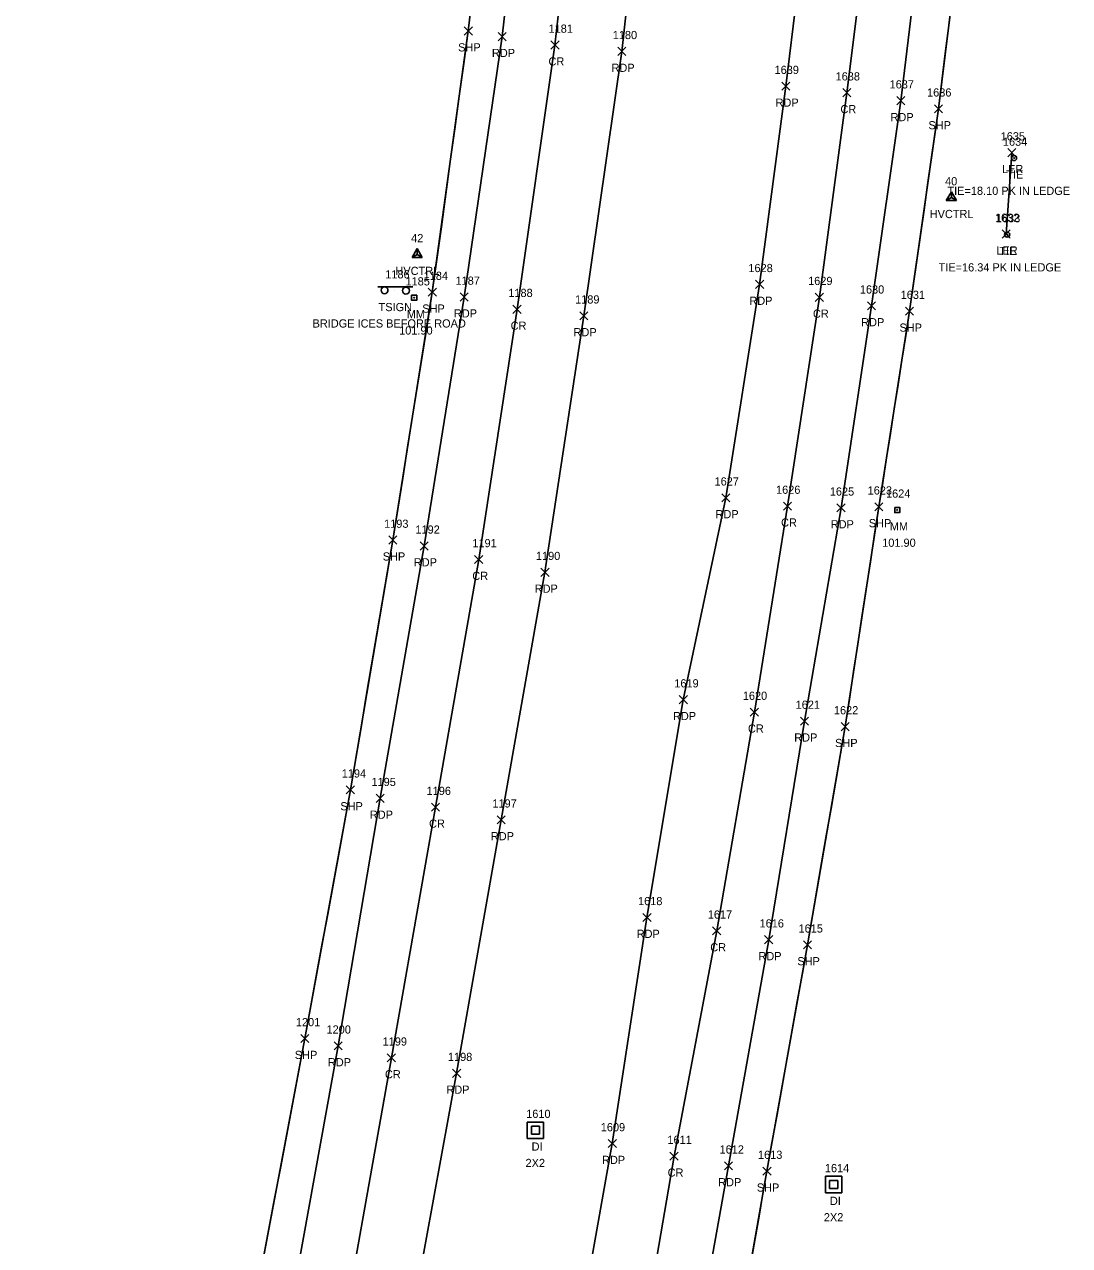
# Model space of a CAD drawing. Extents: x 1472022 to 1479249, y 777216 to 786527.
# Drawn here: x 1473774.1 to 1474029.4, y 780876.1 to 781174.4 of the extents above; entities that cross this region are included whole.
import ezdxf

# ---------------------------------------------------------------- set-up
doc = ezdxf.new("R2010")
doc.units = 0
for name, color, linetype in [('C_A', 7, 'Continuous'), ('C_C', 7, 'Continuous'), ('C_I', 7, 'Continuous'), ('CBP', 7, 'Continuous'), ('CPSM', 7, 'Continuous'), ('D_A', 7, 'Continuous'), ('D_C', 7, 'Continuous'), ('D_I', 7, 'Continuous'), ('DS', 7, 'Continuous'), ('L_A', 7, 'Continuous'), ('L_I', 7, 'Continuous'), ('L_TIC', 7, 'Continuous'), ('LARO', 7, 'Continuous'), ('LSOGP', 7, 'Continuous'), ('P_A', 7, 'Continuous'), ('P_I', 7, 'Continuous'), ('P_TIC', 7, 'Continuous'), ('PET', 7, 'Continuous'), ('PRC', 7, 'Continuous'), ('PSP', 7, 'Continuous'), ('S_A', 7, 'Continuous'), ('S_C', 7, 'Continuous'), ('S_I', 7, 'Continuous'), ('SRM', 7, 'Continuous'), ('SSGN', 7, 'Continuous')]:
    doc.layers.add(name, color=color, linetype=linetype)

msp = doc.modelspace()

# ---------------------------------------------------------------- linework, layer by layer
at = {"layer": 'CBP'}
for centre, radius in [((1474015.88, 781141.74), 0.625), ((1474015.88, 781141.74), 0.0833), ((1474014.18, 781123.04), 0.625), ((1474014.18, 781123.04), 0.0833)]:
    msp.add_circle(centre, radius, dxfattribs=at)
at = {"layer": 'CPSM'}
for p, q in [((1473999.32, 781131.35), (1474000.57, 781133.52)), ((1474001.82, 781131.35), (1474000.57, 781133.52)), ((1474000.57, 781132.07), (1474000.57, 781133.52)), ((1473999.32, 781131.35), (1474000.57, 781132.07)), ((1473999.32, 781131.35), (1474001.82, 781131.35)), ((1474000.57, 781132.07), (1474000.57, 781132.07)), ((1474000.57, 781132.07), (1474001.82, 781131.35)), ((1473868.79, 781117.46), (1473870.04, 781119.62)), ((1473868.79, 781117.46), (1473870.04, 781118.18)), ((1473871.29, 781117.46), (1473870.04, 781119.62)), ((1473870.04, 781118.18), (1473870.04, 781119.62)), ((1473870.04, 781118.18), (1473870.04, 781118.18)), ((1473870.04, 781118.18), (1473871.29, 781117.46)), ((1473868.79, 781117.46), (1473871.29, 781117.46))]:
    msp.add_line(p, q, dxfattribs=at)
at = {"layer": 'DS'}
for p, q in [((1473896.94, 780906.27), (1473900.94, 780906.27)), ((1473896.94, 780902.27), (1473896.94, 780906.27)), ((1473900.94, 780906.27), (1473900.94, 780902.27)), ((1473897.94, 780903.27), (1473897.94, 780905.27)), ((1473897.94, 780905.27), (1473899.94, 780905.27)), ((1473899.94, 780903.27), (1473897.94, 780903.27)), ((1473898.94, 780904.27), (1473898.94, 780904.27)), ((1473898.94, 780904.27), (1473898.94, 780904.27)), ((1473899.94, 780905.27), (1473899.94, 780903.27)), ((1473900.94, 780902.27), (1473896.94, 780902.27)), ((1473969.82, 780893.01), (1473973.82, 780893.01)), ((1473969.82, 780889.01), (1473969.82, 780893.01)), ((1473970.82, 780890.01), (1473970.82, 780892.01)), ((1473970.82, 780892.01), (1473972.82, 780892.01)), ((1473972.82, 780892.01), (1473972.82, 780890.01)), ((1473973.82, 780893.01), (1473973.82, 780889.01)), ((1473973.82, 780889.01), (1473969.82, 780889.01)), ((1473972.82, 780890.01), (1473970.82, 780890.01)), ((1473971.82, 780891.01), (1473971.82, 780891.01)), ((1473971.82, 780891.01), (1473971.82, 780891.01))]:
    msp.add_line(p, q, dxfattribs=at)
at = {"layer": 'L_TIC'}
for points in [[(1474014.34, 781142.05), (1474016.34, 781144.05)], [(1474016.34, 781142.05), (1474014.34, 781144.05)], [(1474012.96, 781122.17), (1474014.96, 781124.17)], [(1474014.96, 781122.17), (1474012.96, 781124.17)]]:
    msp.add_lwpolyline(points, dxfattribs=at)
at = {"layer": 'LARO'}
msp.add_lwpolyline([(1474013.96, 781123.17), (1474015.34, 781143.05)], dxfattribs=at)
at = {"layer": 'LSOGP'}
for points in [[(1473951.63, 780872.29), (1473952.59, 780877.78), (1473953.56, 780883.28), (1473954.52, 780888.77), (1473955.49, 780894.27), (1473956.73, 780901.18), (1473957.96, 780908.09), (1473959.2, 780915), (1473960.44, 780921.91), (1473961.68, 780928.82), (1473962.91, 780935.73), (1473964.15, 780942.64), (1473965.39, 780949.55), (1473966.54, 780956.22), (1473967.69, 780962.88), (1473968.84, 780969.54), (1473970, 780976.21), (1473971.15, 780982.87), (1473972.3, 780989.53), (1473973.45, 780996.19), (1473974.6, 781002.86), (1473975.63, 781009.57), (1473976.66, 781016.28), (1473977.69, 781022.99), (1473978.72, 781029.7), (1473979.75, 781036.42), (1473980.78, 781043.13), (1473981.81, 781049.84), (1473982.84, 781056.55), (1473983.78, 781062.52), (1473984.72, 781068.5), (1473985.66, 781074.47), (1473986.59, 781080.44), (1473987.53, 781086.41), (1473988.47, 781092.38), (1473989.41, 781098.36), (1473990.34, 781104.33), (1473991.23, 781110.51), (1473992.11, 781116.69), (1473993, 781122.87), (1473993.88, 781129.05), (1473994.76, 781135.23), (1473995.65, 781141.41), (1473996.53, 781147.58), (1473997.41, 781153.76), (1473998.24, 781160.53), (1473999.08, 781167.31), (1473999.91, 781174.08), (1474000.74, 781180.85)], [(1473883.42, 781180.21), (1473882.53, 781172.78), (1473881.43, 781164.8), (1473880.33, 781156.83), (1473879.24, 781148.85), (1473878.14, 781140.88), (1473877.04, 781132.9), (1473875.95, 781124.92), (1473874.85, 781116.95), (1473873.75, 781108.97), (1473872.54, 781101.4), (1473871.34, 781093.83), (1473870.13, 781086.26), (1473868.92, 781078.7), (1473867.71, 781071.13), (1473866.51, 781063.56), (1473865.3, 781055.99), (1473864.09, 781048.42), (1473862.8, 781040.79), (1473861.5, 781033.17), (1473860.21, 781025.54), (1473858.92, 781017.91), (1473857.62, 781010.29), (1473856.33, 781002.66), (1473855.04, 780995.03), (1473853.74, 780987.41), (1473852.35, 780979.81), (1473850.96, 780972.22), (1473849.57, 780964.63), (1473848.18, 780957.04), (1473846.79, 780949.45), (1473845.39, 780941.86), (1473844, 780934.26), (1473842.61, 780926.67), (1473841.13, 780918.86), (1473839.66, 780911.04), (1473838.18, 780903.23), (1473836.7, 780895.41), (1473835.22, 780887.6), (1473833.75, 780879.79), (1473832.27, 780871.97)]]:
    msp.add_lwpolyline(points, dxfattribs=at)
at = {"layer": 'P_TIC'}
for points in [[(1473881.53, 781171.78), (1473883.53, 781173.78)], [(1473883.53, 781171.78), (1473881.53, 781173.78)], [(1473889.82, 781170.41), (1473891.82, 781172.41)], [(1473891.82, 781170.41), (1473889.82, 781172.41)], [(1473902.7, 781168.35), (1473904.7, 781170.35)], [(1473904.7, 781168.35), (1473902.7, 781170.35)], [(1473919.04, 781166.79), (1473921.04, 781168.79)], [(1473921.04, 781166.79), (1473919.04, 781168.79)], [(1473959.11, 781158.28), (1473961.11, 781160.28)], [(1473961.11, 781158.28), (1473959.11, 781160.28)], [(1473974.01, 781156.69), (1473976.01, 781158.69)], [(1473976.01, 781156.69), (1473974.01, 781158.69)], [(1473987.2, 781154.74), (1473989.2, 781156.74)], [(1473989.2, 781154.74), (1473987.2, 781156.74)], [(1473996.41, 781152.76), (1473998.41, 781154.76)], [(1473998.41, 781152.76), (1473996.41, 781154.76)], [(1473952.71, 781109.88), (1473954.71, 781111.88)], [(1473954.71, 781109.88), (1473952.71, 781111.88)], [(1473872.75, 781107.97), (1473874.75, 781109.97)], [(1473874.75, 781107.97), (1473872.75, 781109.97)], [(1473880.54, 781106.79), (1473882.54, 781108.79)], [(1473882.54, 781106.79), (1473880.54, 781108.79)], [(1473967.3, 781106.73), (1473969.3, 781108.73)], [(1473969.3, 781106.73), (1473967.3, 781108.73)], [(1473980.03, 781104.64), (1473982.03, 781106.64)], [(1473982.03, 781104.64), (1473980.03, 781106.64)], [(1473893.45, 781103.8), (1473895.45, 781105.8)], [(1473895.45, 781103.8), (1473893.45, 781105.8)], [(1473909.76, 781102.2), (1473911.76, 781104.2)], [(1473911.76, 781102.2), (1473909.76, 781104.2)], [(1473989.34, 781103.33), (1473991.34, 781105.33)], [(1473991.34, 781103.33), (1473989.34, 781105.33)], [(1473944.44, 781057.75), (1473946.44, 781059.75)], [(1473946.44, 781057.75), (1473944.44, 781059.75)], [(1473959.52, 781055.72), (1473961.52, 781057.72)], [(1473961.52, 781055.72), (1473959.52, 781057.72)], [(1473972.6, 781055.28), (1473974.6, 781057.28)], [(1473974.6, 781055.28), (1473972.6, 781057.28)], [(1473981.84, 781055.55), (1473983.84, 781057.55)], [(1473983.84, 781055.55), (1473981.84, 781057.55)], [(1473863.09, 781047.42), (1473865.09, 781049.42)], [(1473865.09, 781047.42), (1473863.09, 781049.42)], [(1473870.75, 781045.99), (1473872.75, 781047.99)], [(1473872.75, 781045.99), (1473870.75, 781047.99)], [(1473884.09, 781042.68), (1473886.09, 781044.68)], [(1473886.09, 781042.68), (1473884.09, 781044.68)], [(1473900.27, 781039.55), (1473902.27, 781041.55)], [(1473902.27, 781039.55), (1473900.27, 781041.55)], [(1473934.05, 781008.43), (1473936.05, 781010.43)], [(1473936.05, 781008.43), (1473934.05, 781010.43)], [(1473951.43, 781005.39), (1473953.43, 781007.39)], [(1473953.43, 781005.39), (1473951.43, 781007.39)], [(1473963.68, 781003.2), (1473965.68, 781005.2)], [(1473965.68, 781003.2), (1473963.68, 781005.2)], [(1473973.6, 781001.86), (1473975.6, 781003.86)], [(1473975.6, 781001.86), (1473973.6, 781003.86)], [(1473852.74, 780986.41), (1473854.74, 780988.41)], [(1473854.74, 780986.41), (1473852.74, 780988.41)], [(1473860.01, 780984.34), (1473862.01, 780986.34)], [(1473862.01, 780984.34), (1473860.01, 780986.34)], [(1473873.53, 780982.16), (1473875.53, 780984.16)], [(1473875.53, 780982.16), (1473873.53, 780984.16)], [(1473889.55, 780979.09), (1473891.55, 780981.09)], [(1473891.55, 780979.09), (1473889.55, 780981.09)], [(1473925.18, 780955.24), (1473927.18, 780957.24)], [(1473927.18, 780955.24), (1473925.18, 780957.24)], [(1473942.22, 780951.96), (1473944.22, 780953.96)], [(1473944.22, 780951.96), (1473942.22, 780953.96)], [(1473954.93, 780949.79), (1473956.93, 780951.79)], [(1473956.93, 780949.79), (1473954.93, 780951.79)], [(1473964.39, 780948.55), (1473966.39, 780950.55)], [(1473966.39, 780948.55), (1473964.39, 780950.55)], [(1473841.61, 780925.67), (1473843.61, 780927.67)], [(1473843.61, 780925.67), (1473841.61, 780927.67)], [(1473849.75, 780923.87), (1473851.75, 780925.87)], [(1473851.75, 780923.87), (1473849.75, 780925.87)], [(1473862.74, 780920.94), (1473864.74, 780922.94)], [(1473864.74, 780920.94), (1473862.74, 780922.94)], [(1473878.69, 780917.18), (1473880.69, 780919.18)], [(1473880.69, 780917.18), (1473878.69, 780919.18)], [(1473916.72, 780900.01), (1473918.72, 780902.01)], [(1473918.72, 780900.01), (1473916.72, 780902.01)], [(1473931.8, 780896.93), (1473933.8, 780898.93)], [(1473933.8, 780896.93), (1473931.8, 780898.93)], [(1473945.09, 780894.57), (1473947.09, 780896.57)], [(1473947.09, 780894.57), (1473945.09, 780896.57)], [(1473954.49, 780893.27), (1473956.49, 780895.27)], [(1473956.49, 780893.27), (1473954.49, 780895.27)]]:
    msp.add_lwpolyline(points, dxfattribs=at)
at = {"layer": 'PET'}
for points in [[(1473897.58, 781231.34), (1473890.82, 781171.41), (1473881.54, 781107.79), (1473871.75, 781046.99), (1473861.01, 780985.34), (1473850.75, 780924.87), (1473839.34, 780861.82), (1473828.24, 780801.17), (1473817.32, 780741.26), (1473806.09, 780678.1), (1473794.13, 780615.24), (1473782.52, 780552.37)], [(1473926.74, 781228.4), (1473920.04, 781167.79), (1473910.76, 781103.2), (1473901.27, 781040.55), (1473890.55, 780980.09), (1473879.69, 780918.18), (1473868.45, 780856.64), (1473857.58, 780795.65), (1473846.42, 780735.85), (1473834.5, 780671.46), (1473823.42, 780612.39), (1473811.33, 780545.89)], [(1473858.97, 780579.12), (1473867.36, 780624.13), (1473877.11, 780675.98), (1473886.11, 780727.43), (1473894.33, 780770.7), (1473900.97, 780808.51), (1473909.58, 780855.22), (1473917.72, 780901.01), (1473926.18, 780956.24), (1473935.05, 781009.43), (1473945.44, 781058.75), (1473953.71, 781110.88), (1473960.11, 781159.28), (1473966.39, 781210.69)], [(1473887.71, 780574.3), (1473895.6, 780618.75), (1473905.45, 780670.32), (1473914.28, 780720.97), (1473922.71, 780765.55), (1473929.03, 780802.44), (1473938.07, 780850.55), (1473946.09, 780895.57), (1473955.93, 780950.79), (1473964.68, 781004.2), (1473973.6, 781056.28), (1473981.03, 781105.64), (1473988.2, 781155.74), (1473994.49, 781207.67)]]:
    msp.add_lwpolyline(points, dxfattribs=at)
at = {"layer": 'PRC'}
for points in [[(1473910.61, 781230.26), (1473903.7, 781169.35), (1473894.45, 781104.8), (1473885.09, 781043.68), (1473874.53, 780983.16), (1473863.74, 780921.94), (1473852.71, 780859.81), (1473841.54, 780798.62), (1473830.32, 780739.37), (1473818.72, 780674.7), (1473807.59, 780614.57), (1473795.53, 780548.63)], [(1473874.56, 780576.61), (1473882.64, 780621.02), (1473892.2, 780672.57), (1473901.35, 780723.23), (1473910.11, 780767.82), (1473915.89, 780804.48), (1473924.97, 780851.96), (1473932.8, 780897.93), (1473943.22, 780952.96), (1473952.43, 781006.39), (1473960.52, 781056.72), (1473968.3, 781107.73), (1473975.01, 781157.69), (1473981.49, 781209.1)]]:
    msp.add_lwpolyline(points, dxfattribs=at)
at = {"layer": 'PSP'}
for points in [[(1473889.69, 781232.26), (1473882.53, 781172.78), (1473873.75, 781108.97), (1473864.09, 781048.42), (1473853.74, 780987.41), (1473842.61, 780926.67), (1473830.79, 780864.16), (1473819.66, 780802.9), (1473808.62, 780742.26), (1473797.28, 780680.22), (1473785.49, 780617.45), (1473774.09, 780553.9)], [(1473897.21, 780573.03), (1473905.39, 780617.74), (1473914.98, 780669.02), (1473924.04, 780718.8), (1473932.36, 780764.14), (1473938.69, 780801.17), (1473947.77, 780850.3), (1473955.49, 780894.27), (1473965.39, 780949.55), (1473974.6, 781002.86), (1473982.84, 781056.55), (1473990.34, 781104.33), (1473997.41, 781153.76), (1474004.06, 781207.93)]]:
    msp.add_lwpolyline(points, dxfattribs=at)
at = {"layer": 'SRM'}
for points in [[(1473868.69, 781108.24), (1473869.94, 781108.24), (1473869.94, 781106.99), (1473868.69, 781106.99)], [(1473986.71, 781056.4), (1473987.96, 781056.4), (1473987.96, 781055.15), (1473986.71, 781055.15)]]:
    msp.add_lwpolyline(points, close=True, dxfattribs=at)
for centre in [(1473869.32, 781107.62), (1473987.33, 781055.78)]:
    msp.add_circle(centre, 0.0833, dxfattribs=at)
at = {"layer": 'SSGN'}
for p, q in [((1473860.42, 781110.26), (1473869.02, 781110.26)), ((1473864.44, 781109.36), (1473864.44, 781109.36))]:
    msp.add_line(p, q, dxfattribs=at)
for centre in [(1473862.08, 781109.43), (1473867.3, 781109.36)]:
    msp.add_circle(centre, 0.833, dxfattribs=at)

# ---------------------------------------------------------------- texts
at = {"layer": 'C_A'}
for s, p in [('TIE', (1474013.96, 781136.74)), ('HVCTRL', (1473995.27, 781127.07)), ('TIE', (1474012.26, 781118.04)), ('HVCTRL', (1473864.73, 781113.18))]:
    msp.add_text(s, height=2, dxfattribs=at).set_placement(p)
at = {"layer": 'C_C'}
for s, p in [('TIE=18.10 PK IN LEDGE', (1473999.6, 781132.74)), ('TIE=16.34 PK IN LEDGE', (1473997.44, 781114.04))]:
    msp.add_text(s, height=2, dxfattribs=at).set_placement(p)
at = {"layer": 'C_I'}
for s, p in [('1634', (1474013.14, 781144.74)), ('40', (1473999.02, 781135.07)), ('1633', (1474011.44, 781126.04)), ('42', (1473868.57, 781121.18))]:
    msp.add_text(s, height=2, dxfattribs=at).set_placement(p)
at = {"layer": 'D_A'}
for p in [(1473898, 780899.27), (1473970.88, 780886.01)]:
    msp.add_text('DI', height=2, dxfattribs=at).set_placement(p)
at = {"layer": 'D_C'}
for p in [(1473896.52, 780895.27), (1473969.4, 780882.01)]:
    msp.add_text('2X2', height=2, dxfattribs=at).set_placement(p)
at = {"layer": 'D_I'}
for s, p in [('1610', (1473896.68, 780907.27)), ('1614', (1473969.65, 780894.01))]:
    msp.add_text(s, height=2, dxfattribs=at).set_placement(p)
at = {"layer": 'L_A'}
for p in [(1474012.92, 781138.05), (1474011.55, 781118.17)]:
    msp.add_text('LER', height=2, dxfattribs=at).set_placement(p)
at = {"layer": 'L_I'}
for s, p in [('1635', (1474012.6, 781146.05)), ('1632', (1474011.22, 781126.17))]:
    msp.add_text(s, height=2, dxfattribs=at).set_placement(p)
at = {"layer": 'P_A'}
for s, p in [('SHP', (1473880.06, 781167.78)), ('RDP', (1473888.31, 781166.41)), ('CR', (1473902.13, 781164.35)), ('RDP', (1473917.53, 781162.79)), ('RDP', (1473957.6, 781154.28)), ('CR', (1473973.45, 781152.69)), ('RDP', (1473985.69, 781150.74)), ('SHP', (1473994.95, 781148.76)), ('SHP', (1473871.29, 781103.97)), ('RDP', (1473951.2, 781105.88)), ('RDP', (1473879.02, 781102.79)), ('CR', (1473966.74, 781102.73)), ('CR', (1473892.88, 781099.8)), ('RDP', (1473908.25, 781098.2)), ('RDP', (1473978.52, 781100.64)), ('SHP', (1473987.88, 781099.33)), ('RDP', (1473942.93, 781053.75)), ('CR', (1473958.95, 781051.72)), ('RDP', (1473971.09, 781051.28)), ('SHP', (1473980.38, 781051.55)), ('SHP', (1473861.63, 781043.42)), ('RDP', (1473869.23, 781041.99)), ('CR', (1473883.52, 781038.68)), ('RDP', (1473898.76, 781035.55)), ('RDP', (1473932.54, 781004.43)), ('CR', (1473950.86, 781001.39)), ('RDP', (1473962.17, 780999.2)), ('SHP', (1473972.14, 780997.86)), ('SHP', (1473851.28, 780982.41)), ('RDP', (1473858.49, 780980.34)), ('CR', (1473872.96, 780978.16)), ('RDP', (1473888.04, 780975.09)), ('RDP', (1473923.67, 780951.24)), ('CR', (1473941.65, 780947.96)), ('RDP', (1473953.42, 780945.79)), ('SHP', (1473962.93, 780944.55)), ('SHP', (1473840.15, 780921.67)), ('RDP', (1473848.24, 780919.87)), ('CR', (1473862.17, 780916.94)), ('RDP', (1473877.18, 780913.18)), ('RDP', (1473915.21, 780896.01)), ('CR', (1473931.23, 780892.93)), ('RDP', (1473943.58, 780890.57)), ('SHP', (1473953.02, 780889.27))]:
    msp.add_text(s, height=2, dxfattribs=at).set_placement(p)
at = {"layer": 'P_I'}
for s, p in [('1181', (1473902.14, 781172.35)), ('1180', (1473917.83, 781170.79)), ('1639', (1473957.36, 781162.28)), ('1638', (1473972.27, 781160.69)), ('1637', (1473985.46, 781158.74)), ('1636', (1473994.62, 781156.76)), ('1628', (1473950.97, 781113.88)), ('1184', (1473871.63, 781111.97)), ('1187', (1473879.41, 781110.79)), ('1629', (1473965.56, 781110.73)), ('1188', (1473892.32, 781107.8)), ('1630', (1473978.2, 781108.64)), ('1631', (1473988.17, 781107.33)), ('1189', (1473908.63, 781106.2)), ('1627', (1473942.7, 781061.75)), ('1626', (1473957.72, 781059.72)), ('1625', (1473970.86, 781059.28)), ('1623', (1473980.1, 781059.55)), ('1193', (1473861.97, 781051.42)), ('1192', (1473869.62, 781049.99)), ('1191', (1473883.53, 781046.68)), ('1190', (1473899.06, 781043.55)), ('1619', (1473932.87, 781012.43)), ('1620', (1473949.6, 781009.39)), ('1621', (1473962.51, 781007.2)), ('1622', (1473971.86, 781005.86)), ('1194', (1473851.62, 780990.41)), ('1195', (1473858.88, 780988.34)), ('1196', (1473872.35, 780986.16)), ('1197', (1473888.43, 780983.09)), ('1618', (1473924.01, 780959.24)), ('1617', (1473941.05, 780955.96)), ('1616', (1473953.7, 780953.79)), ('1615', (1473963.22, 780952.55)), ('1201', (1473840.41, 780929.67)), ('1200', (1473847.9, 780927.87)), ('1199', (1473861.61, 780924.94)), ('1198', (1473877.56, 780921.18)), ('1609', (1473914.9, 780904.01)), ('1611', (1473931.19, 780900.93)), ('1612', (1473943.92, 780898.57)), ('1613', (1473953.31, 780897.27))]:
    msp.add_text(s, height=2, dxfattribs=at).set_placement(p)
at = {"layer": 'S_A'}
for s, p in [('TSIGN', (1473860.62, 781104.34)), ('MM', (1473867.5, 781102.62)), ('MM', (1473985.52, 781050.78))]:
    msp.add_text(s, height=2, dxfattribs=at).set_placement(p)
at = {"layer": 'S_C'}
for s, p in [('BRIDGE ICES BEFORE ROAD', (1473844.49, 781100.34)), ('101.90', (1473865.64, 781098.62)), ('101.90', (1473983.66, 781046.78))]:
    msp.add_text(s, height=2, dxfattribs=at).set_placement(p)
at = {"layer": 'S_I'}
for s, p in [('1186', (1473862.26, 781112.34)), ('1185', (1473867.19, 781110.62)), ('1624', (1473984.59, 781058.78))]:
    msp.add_text(s, height=2, dxfattribs=at).set_placement(p)

doc.saveas('drawing.dxf')
